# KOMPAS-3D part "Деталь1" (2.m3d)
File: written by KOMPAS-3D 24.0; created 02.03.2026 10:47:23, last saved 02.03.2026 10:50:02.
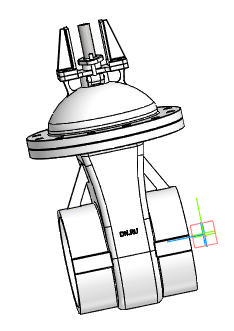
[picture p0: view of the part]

Document properties: Автор: R2D2; Полное имя файла: E:\Работа\Зайцев\GVWR2121M-2W-F-ОСТ Задвижка клиновая с видвижным штоком Ду50-300 Ру16\DN250\Исходные материалы\2.m3d

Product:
- Body: Твердое тело1  | qty 1
    Масса: 135.40649
- Part/product: Деталь1
    Масса: 135.40649
    additional columns: Типовые

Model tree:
1. Твердое тело1  (labels: Твердое тело1)
2. Эскиз:1
3. Элемент выдавливания:2
     Расстояние 1 = 500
